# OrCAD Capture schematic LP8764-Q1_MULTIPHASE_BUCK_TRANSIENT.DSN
size B
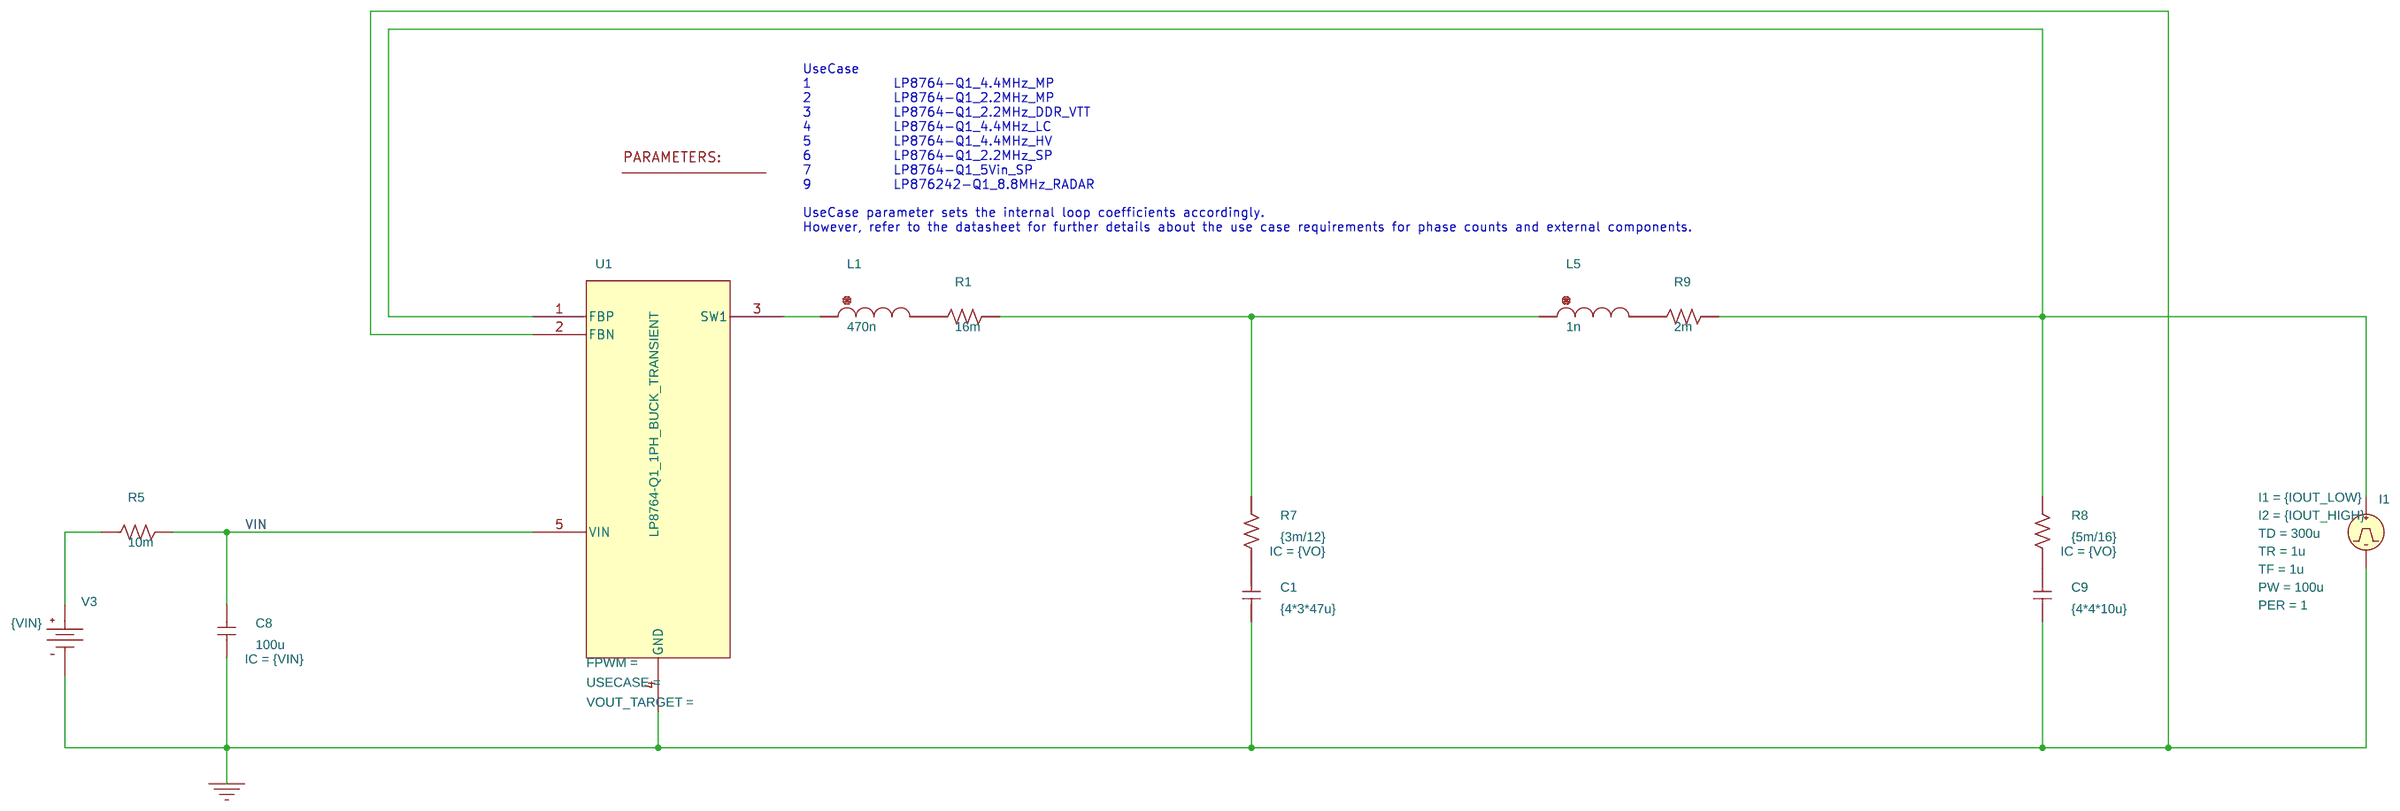
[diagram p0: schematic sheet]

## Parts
2  PARAM
C1  {4*3*47u}  [cap196]
C8  100u  [RAD/CK05]
C9  {4*4*10u}  [cap196]
I1  IPULSE
L1  470n  [DISC350x175LS200x100034]
L5  1n  [DISC350x175LS200x100034]
R1  16m  [AXRC05]
R5  10m  [AX/RC05]
R7  {3m/12}  [AXRC05]
R8  {5m/16}  [AXRC05]
R9  2m  [AXRC05]
U1  LP8764-Q1_1PH_BUCK_TRANSIENT
V3  VDC

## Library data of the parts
2 = PARAM: IOUT_HIGH: 4; IOUT_LOW: 1m; VIN: 3.3; VO: 1
C1 C9 = C: IC: {VO}
C8 = C: IC: {VIN}
I1 = IPULSE: I1: {IOUT_LOW}; I2: {IOUT_HIGH}; PER: 1; PW: 100u; TD: 300u; TF: 1u; TR: 1u
L1 L5 = L: IC: {IOUT_LOW/4}
R1 R5 R7-R9 = R
U1 = LP8764-Q1_1PH_BUCK_TRANSIENT
V3 = VDC: DC: {VIN}

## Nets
VIN: C8.1 R5.2 U1.5(VIN)
0: C1.2 C8.2 C9.2 I1.2(-) U1.2(FBN) U1.4(GND) V3.1(-)
N24181: I1.1(+) R8.2 R9.2 U1.1(FBP)
N24317: L1.1 U1.3(SW1)
N24323: L5.1 R1.2 R7.2
N24635: R5.1 V3.0(+)
N27285: C9.1 R8.1
N27286: C1.1 R7.1
N27287: L5.2 R9.1
N27288: L1.2 R1.1

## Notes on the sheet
- UseCase
  1            LP8764-Q1_4.4MHz_MP
  2            LP8764-Q1_2.2MHz_MP
  3            LP8764-Q1_2.2MHz_DDR_VTT
  4            LP8764-Q1_4.4MHz_LC
  5            LP8764-Q1_4.4MHz_HV
  6            LP8764-Q1_2.2MHz_SP
  7            LP8764-Q1_5Vin_SP
  9            LP876242-Q1_8.8MHz_RADAR
- UseCase parameter sets the internal loop coefficients accordingly.
  However, refer to the datasheet for further details about the use case requirements for phase counts and external components.
